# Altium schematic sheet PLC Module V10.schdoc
size A4; SheetNumber: 1; SheetTotal: 1
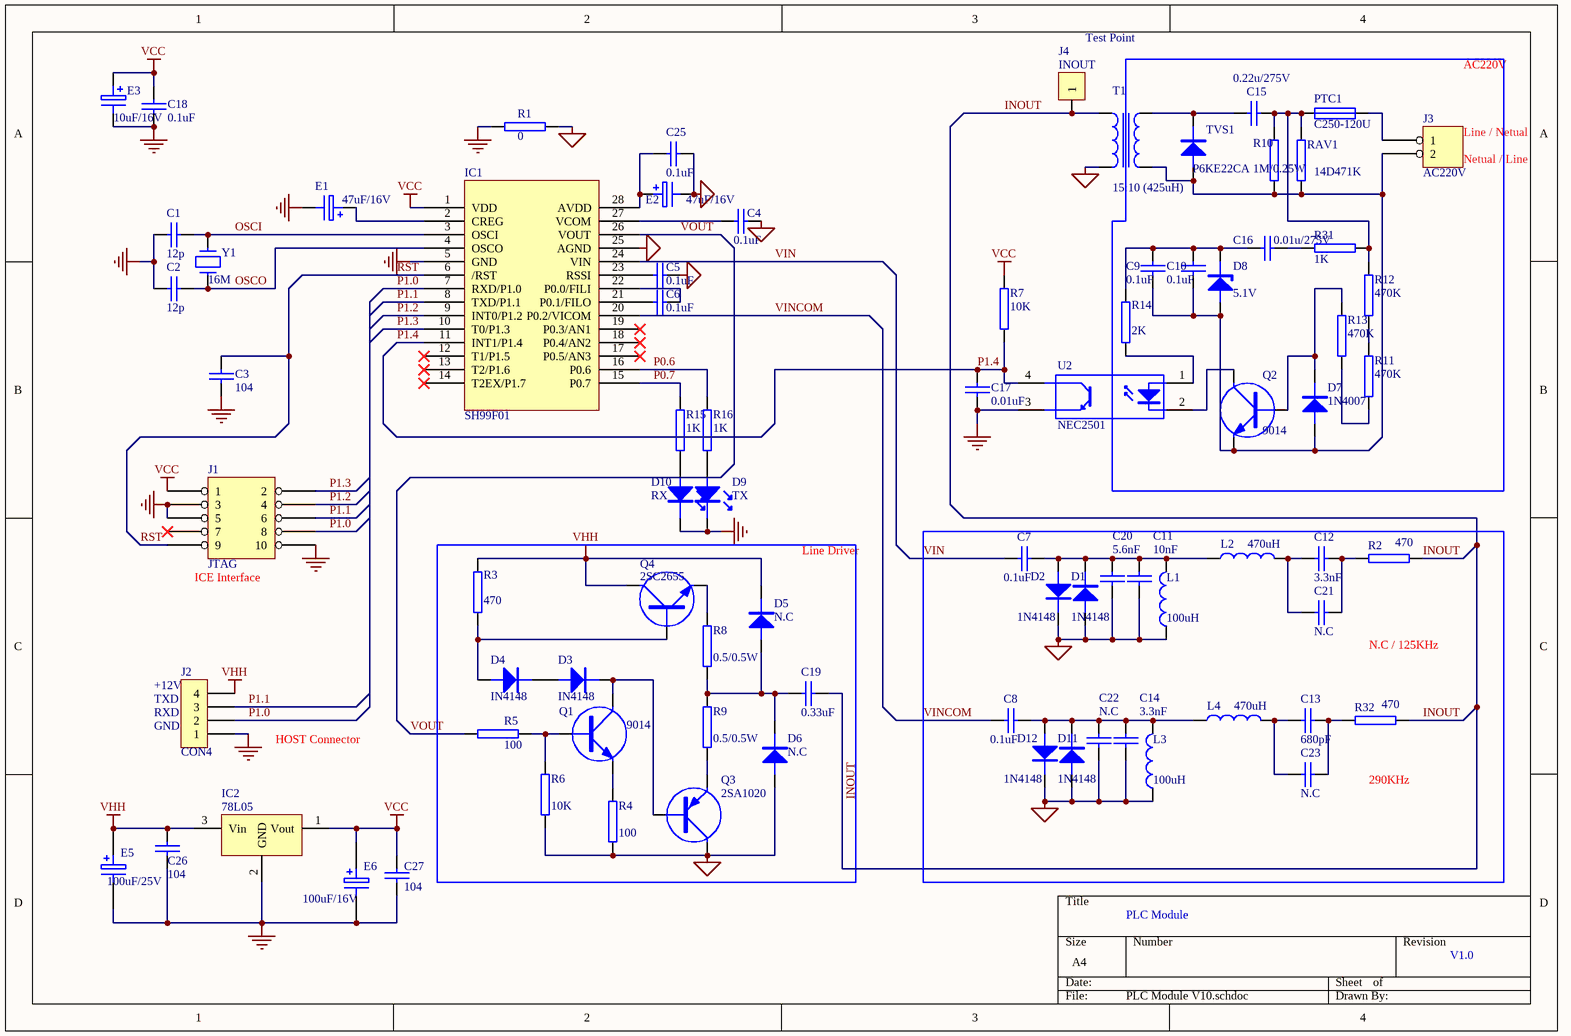
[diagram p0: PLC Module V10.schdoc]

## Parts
C1  12p  [0603]
C2  12p  [0603]
C3  104  [0603]
C4  0.1uF  [0603]
C5  0.1uF  [0603]
C6  0.1uF  [0603]
C7  0.1uF  [0603]
C8  0.1uF  [0603]
C9  0.1uF  [RAD0.1]
C10  0.1uF  [RAD0.1]
C11  10nF  [0603]
C12  3.3nF  [0603]
C13  680pF  [0603]
C14  3.3nF  [0603]
C15  0.22u/275V  [RAD-0.6]
C16  0.01u/275V  [RAD-0.4]
C17  0.01uF  [0603]
C18  0.1uF  [0603]
C19  0.33uF  [RAD0.1]
C20  5.6nF  [0603]
C21  N.C  [0603]
C22  N.C  [0603]
C23  N.C  [0603]
C25  0.1uF  [0603]
C26  104  [0603]
C27  104  [0603]
D1  1N4148  [SOD323]
D2  1N4148  [SOD323]
D3  IN4148  [SOD323]
D4  IN4148  [SOD323]
D5  N.C  [SOD323]
D6  N.C  [SOD323]
D7  1N4007  [DIODE0.1]
D8  5.1V  [DIODE0.1]
D9  TX  [0603-D]
D10  RX  [0603-D]
D11  1N4148  [SOD323]
D12  1N4148  [SOD323]
E1  47uF/16V  [3528(B)]
E2  47uF/16V  [3528(B)]
E3  10uF/16V  [3216(A)]
E5  100uF/25V  [7343(D)]
E6  100uF/16V  [6032(C)]
IC1  SH99F01  [TSSOP28]
IC2  78L05  [TO-92B]
J1  JTAG  [IDC10]
J2  CON4  [SIP4]
J3  AC220V  [SIP2W]
J4  INOUT  [SIP1]
L1  100uH  [1210]
L2  470uH  [1210]
L3  100uH  [1210]
L4  470uH  [1210]
PTC1  C250-120U  [AXIAL0.3]
Q1  9014  [SOT323-Q]
Q2  9014  [SOT323-Q]
Q3  2SA1020  [TO-92A]
Q4  2SC2655  [TO-92A]
R1  0  [0603]
R2  470  [0603]
R3  470  [0603]
R4  100  [0603]
R5  100  [0603]
R6  10K  [0603]
R7  10K  [0603]
R8  0.5/0.5W  [0805]
R9  0.5/0.5W  [0805]
R10  1M/0.25W  [AXIAL0.3]
R11  470K  [AXIAL0.3]
R12  470K  [AXIAL0.3]
R13  470K  [AXIAL0.3]
R14  2K  [AXIAL0.3]
R15  1K  [0603]
R16  1K  [0603]
R31  1K  [AXIAL0.4]
R32  470  [0603]
RAV1  14D471K  [ZNR]
T1  15:10 (425uH)  [TRANS5]
TVS1  P6KE22CA  [DIODE0.1]
U2  NEC2501  [TLP]
Y1  16M  [CRY2]

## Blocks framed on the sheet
Line Driver: C19 D3-D6 Q1 Q3 Q4 R3-R6 R8 R9

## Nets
AGND: C4.2 C5.2 C11.1 C14.1 C20.1 C22.1 C25.2 D1.A D2.K D6.A D11.A D12.K E2.2 IC1.25(AGND) L1.1 L3.1 Q3.C R1.2 R4.2 R6.2 T1.4
GND: C1.2 C2.2 C3.2 C17.1 C18.2 C26.2 C27.2 D9.K D10.K E1.2 E3.2 E5.2 E6.2 IC1.5(GND) IC2.2(GND) J1.3 J1.5 J1.10 J2.1 R1.1 U2.3(E)
VCC: C18.1 C27.1 E3.1 E6.1 IC1.1(VDD) IC2.1(Vout) J1.1 R7.2
VHH: C26.1 D5.K E5.1 IC2.3(Vin) J2.4 Q4.C R3.1
INOUT: C19.2 J4.1 R2.2 R32.2 T1.2
OSCI: C1.1 IC1.3(OSCI) Y1.2
OSCO: C2.1 IC1.4(OSCO) Y1.1
P0.6: IC1.16(P0.6) R16.2
P0.7: IC1.15(P0.7) R15.1
P1.0: IC1.7(RXD/P1.0) J1.8 J2.2
P1.1: IC1.8(TXD/P1.1) J1.6 J2.3
P1.2: IC1.9(INT0/P1.2) J1.4
P1.3: IC1.10(T0/P1.3) J1.2
P1.4: C17.2 IC1.11(INT1/P1.4) R7.1 U2.4(C)
RST: C3.1 IC1.6(/RST) J1.9
VIN: C7.1 IC1.24(VIN)
VINCOM: C8.1 IC1.20(P0.2/VICOM)
VOUT: IC1.26(VOUT) R5.2
NetC4_1: C4.1 IC1.27(VCOM)
NetC5_1: C5.1 IC1.23(RSSI)
NetC6_1: C6.1 IC1.21(P0.1/FILO)
NetC6_2: C6.2 IC1.22(P0.0/FILI)
NetC7_2: C7.2 C11.2 C20.2 D1.K D2.A L1.2 L2.1
NetC8_2: C8.2 C14.2 C22.2 D11.K D12.A L3.2 L4.1
NetC9_1: C9.1 C10.1 D7.A D8.A J3.2 Q2.E R10.2 RAV1.1 T1.3 TVS1.A
NetC9_2: C9.2 C10.2 C16.2 D8.K R14.1
NetC12_1: C12.1 C21.1 R2.1
NetC12_2: C12.2 C21.2 L2.2
NetC13_1: C13.1 C23.1 R32.1
NetC13_2: C13.2 C23.2 L4.2
NetC15_1: C15.1 PTC1.1 R10.1 R12.2 R31.2 RAV1.2
NetC15_2: C15.2 T1.1 TVS1.K
NetC16_1: C16.1 R31.1
NetC19_1: C19.1 D5.A D6.K R8.2 R9.1
NetC25_1: C25.1 E2.1 IC1.28(AVDD)
NetD3_A: D3.A D4.K
NetD3_K: D3.K Q1.C Q3.B
NetD4_A: D4.A Q4.B R3.2
NetD7_K: D7.K Q2.B R13.2
NetD9_A: D9.A R16.1
NetD10_A: D10.A R15.2
NetE1_1: E1.1 IC1.2(CREG)
NetJ3_1: J3.1 PTC1.2
NetQ1_B: Q1.B R5.1 R6.1
NetQ1_E: Q1.E R4.1
NetQ2_C: Q2.C U2.2(K)
NetQ3_E: Q3.E R9.2
NetQ4_E: Q4.E R8.1
NetR11_1: R11.1 R12.1
NetR11_2: R11.2 R13.1
NetR14_2: R14.2 U2.1(A)

Not connected (* = marked no-connect by the designer): IC1 12(T1/P1.5)* 13(T2/P1.6)* 14(T2EX/P1.7)* 17(P0.5/AN3)* 18(P0.4/AN2)* 19(P0.3/AN1)*; J1 7*

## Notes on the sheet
- Test Point
- AC220V
- (near J3) Line / Netual
- (near J3) Netual / Line
- (near J1) ICE Interface
- N.C / 125KHz
- (near J2) +12V
- (near J2) TXD
- (near J2) RXD
- (near J2) GND
- HOST Connector
- 290KHz
- PLC Module
- V1.0

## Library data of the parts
C1 C2 C4-C6 C9-C11 C14 C17 C18 C25 = CAP: Capacitor; Part Field 1: 1
C3 C7 C8 C15 C16 C19 = CAP: Capacitor
C12 C13 C20-C23 = CAP: Capacitor; Part Field 1: +5
C26 C27 = CAP_V: Capacitor
D1 D2 D7 D11 D12 TVS1 = DIODE
D3-D6 = DIODE: Part Field 1: 1
D8 = ZENER1: ZENER; Part Field 1: 1
D9 D10 = LED
E1-E3 = ELECTRO: Part Field 1: 1
E5 E6 = ELECTRO1: Electrolytic Capacitor
IC1 = SH99F01: Part Field 1: 1
IC2 = 78L05: Part Field 1: +5
J1 = HEADER 5X2
J2 = CON4: Connector
J3 = HEADER 2
J4 = CON1
L1 L3 = INDUCTOR: Part Field 1: +12
L2 L4 = INDUCTOR1: Part Field 1: +5
PTC1 = FUSE1
Q1 Q2 Q4 = NPN: Part Field 1: 1
Q3 = PNP: Part Field 1: 1
R1 R2 R31 R32 = RES1: RES; Part Field 1: +5
R3-R6 R8 R9 = RES1: RES; Part Field 1: 1
R7 R10-R14 RAV1 = RES1: RES
R15 R16 = RES2
T1 = TRANS1: TRANS
U2 = OPTOISO1: Optoisolator; Part Field 1: 1
Y1 = CRY2: CRY; Part Field 1: 1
